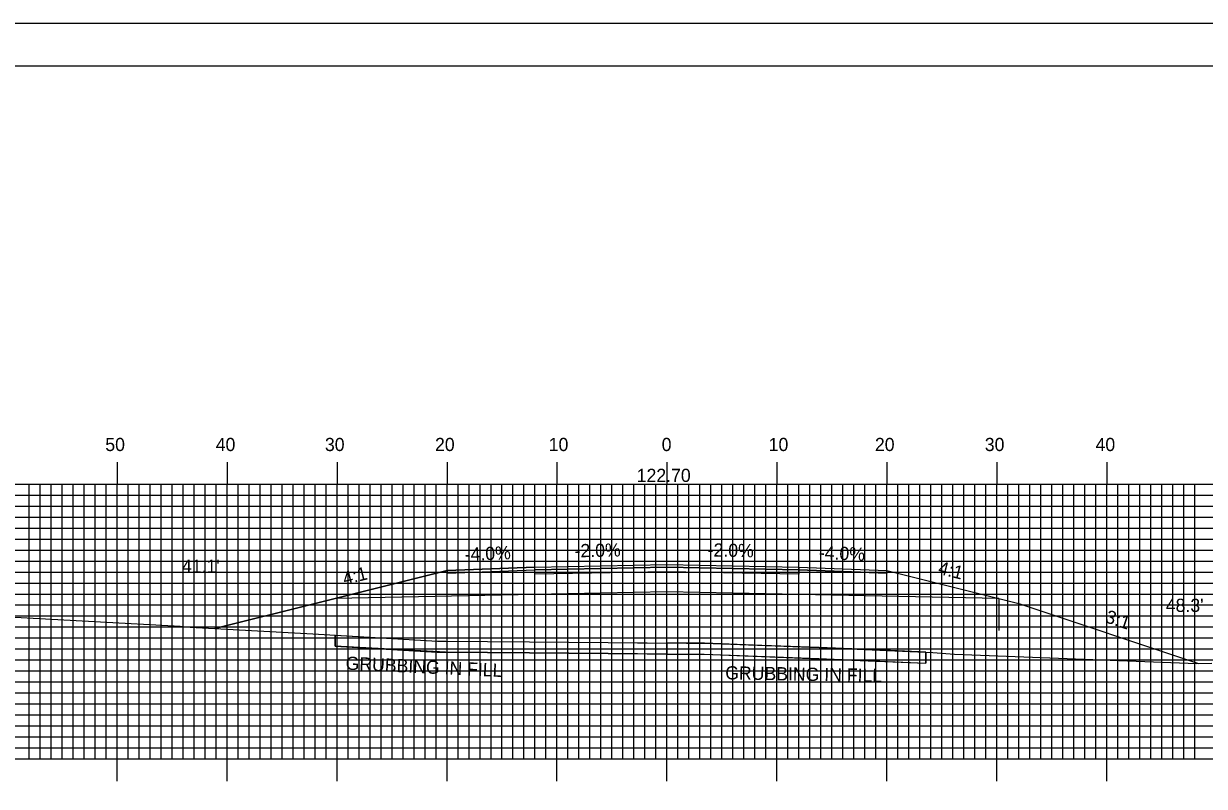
# Model space of a CAD drawing. Extents: x 1780680 to 1781023, y 442591 to 442811.
# Drawn here: x 1780786.9 to 1780894.2, y 442741.2 to 442810.5 of the extents above; entities that cross this region are included whole.
import ezdxf

# ---------------------------------------------------------------- set-up
doc = ezdxf.new("R2010")
doc.units = 0
for name, color, linetype in [('ANNOTATION', 7, 'Continuous'), ('BORDER', 7, 'Continuous'), ('D_Roadway_Centerline', 7, 'Continuous'), ('D_Roadway_Centerline_Text', 7, 'Continuous'), ('D_Roadway_Edge_Shoulder', 7, 'Continuous'), ('D_Roadway_Edge_TW', 7, 'Continuous'), ('D_Roadway_Pavement', 7, 'Continuous'), ('D_Roadway_SlopeLines', 7, 'Continuous'), ('D_Roadway_SubGrade', 7, 'Continuous'), ('D_Text_Standard', 7, 'Continuous'), ('GRUBBING IN FILL', 7, 'Continuous'), ('H_V ANNOTATION', 7, 'Continuous'), ('MAJOR', 7, 'Continuous'), ('MINOR', 7, 'Continuous'), ('PLOT BOUNDARY', 7, 'Continuous'), ('S_Roadway_Centerline', 7, 'Continuous')]:
    doc.layers.add(name, color=color, linetype=linetype)

msp = doc.modelspace()

# ---------------------------------------------------------------- linework, layer by layer
at = {"layer": 'BORDER'}
msp.add_lwpolyline([(1780695.78, 442596.67), (1781015.78, 442596.67), (1781015.78, 442806.67), (1780695.78, 442806.67)], close=True, dxfattribs=at)
at = {"layer": 'D_Roadway_Centerline'}
msp.add_lwpolyline([(1780804.27, 442755.53), (1780813.38, 442757.8), (1780815.21, 442758.26), (1780825.38, 442760.8), (1780833.38, 442761.12), (1780845.38, 442761.36), (1780857.38, 442761.12), (1780865.38, 442760.8), (1780875.56, 442758.26), (1780877.38, 442757.8), (1780893.72, 442752.36)], dxfattribs=at)
at = {"layer": 'D_Roadway_Edge_Shoulder'}
for points in [[(1780833.38, 442761.12), (1780825.38, 442760.8), (1780825.38, 442760.55), (1780833.38, 442760.87)], [(1780857.38, 442761.12), (1780865.38, 442760.8), (1780865.38, 442760.55), (1780857.38, 442760.87)]]:
    msp.add_lwpolyline(points, close=True, dxfattribs=at)
at = {"layer": 'D_Roadway_Edge_TW'}
msp.add_lwpolyline([(1780833.38, 442760.87), (1780833.38, 442761.12), (1780845.38, 442761.36), (1780857.38, 442761.12), (1780857.38, 442760.87), (1780845.38, 442761.11)], close=True, dxfattribs=at)
at = {"layer": 'D_Roadway_Pavement'}
msp.add_lwpolyline([(1780833.38, 442760.46), (1780833.38, 442760.87), (1780845.38, 442761.11), (1780857.38, 442760.87), (1780857.38, 442760.46), (1780845.38, 442760.7)], close=True, dxfattribs=at)
at = {"layer": 'D_Roadway_SlopeLines'}
for points in [[(1780825.38, 442760.8), (1780815.21, 442758.26), (1780813.38, 442757.8), (1780804.27, 442755.53)], [(1780865.38, 442760.8), (1780877.38, 442757.8), (1780893.72, 442752.36)]]:
    msp.add_lwpolyline(points, dxfattribs=at)
at = {"layer": 'D_Roadway_SubGrade'}
msp.add_lwpolyline([(1780833.38, 442758.62), (1780815.21, 442758.26), (1780825.38, 442760.8), (1780825.38, 442760.55), (1780833.38, 442760.87), (1780845.38, 442761.11), (1780857.38, 442760.87), (1780865.38, 442760.55), (1780865.38, 442760.8), (1780875.56, 442758.26), (1780857.38, 442758.62), (1780845.38, 442758.86)], close=True, dxfattribs=at)
at = {"layer": 'GRUBBING IN FILL'}
for p, q in [((1780875.56, 442758.26), (1780875.56, 442755.36)), ((1780875.56, 442758.26), (1780875.56, 442755.36)), ((1780815.21, 442754.92), (1780815.21, 442753.92)), ((1780815.21, 442754.92), (1780815.21, 442753.92)), ((1780868.91, 442753.39), (1780868.91, 442752.39)), ((1780868.91, 442753.39), (1780868.91, 442752.39))]:
    msp.add_line(p, q, dxfattribs=at)
for points in [[(1780815.21, 442753.92), (1780815.21, 442754.92), (1780818.85, 442754.71), (1780824.52, 442754.39), (1780829.07, 442754.35), (1780832.88, 442754.32), (1780840.02, 442754.25), (1780845.38, 442754.2), (1780845.38, 442753.2), (1780840.02, 442753.25), (1780832.87, 442753.32), (1780825.25, 442753.38)], [(1780815.21, 442753.92), (1780815.21, 442754.92), (1780818.85, 442754.71), (1780824.52, 442754.39), (1780829.07, 442754.35), (1780832.88, 442754.32), (1780840.02, 442754.25), (1780845.38, 442754.2), (1780845.38, 442753.2), (1780840.02, 442753.25), (1780832.87, 442753.32), (1780825.25, 442753.38)], [(1780845.38, 442753.2), (1780848.77, 442753.2), (1780853.98, 442753), (1780853.98, 442753), (1780868.91, 442752.39), (1780868.91, 442753.39), (1780864.39, 442753.59), (1780859.23, 442753.81), (1780854.01, 442754), (1780848.79, 442754.2), (1780845.38, 442754.2)], [(1780845.38, 442753.2), (1780848.77, 442753.2), (1780853.98, 442753), (1780853.98, 442753), (1780868.91, 442752.39), (1780868.91, 442753.39), (1780864.39, 442753.59), (1780859.23, 442753.81), (1780854.01, 442754), (1780848.79, 442754.2), (1780845.38, 442754.2)]]:
    msp.add_lwpolyline(points, close=True, dxfattribs=at)
msp.add_lwpolyline([(1780815.21, 442753.92), (1780824.49, 442753.39), (1780825.25, 442753.38), (1780832.87, 442753.32), (1780847.16, 442753.19), (1780847.98, 442753.2), (1780848.77, 442753.2), (1780859.19, 442752.81), (1780868.91, 442752.39)], dxfattribs=at)
msp.add_lwpolyline([(1780815.21, 442753.92), (1780824.49, 442753.39), (1780825.25, 442753.38), (1780832.87, 442753.32), (1780847.16, 442753.19), (1780847.98, 442753.2), (1780848.77, 442753.2), (1780859.19, 442752.81), (1780868.91, 442752.39)], dxfattribs=at)
at = {"layer": 'MAJOR'}
for p, q in [((1780795.38, 442770.67), (1780795.38, 442768.67)), ((1780805.38, 442770.67), (1780805.38, 442768.67)), ((1780815.38, 442770.67), (1780815.38, 442768.67)), ((1780825.38, 442770.67), (1780825.38, 442768.67)), ((1780835.38, 442770.67), (1780835.38, 442768.67)), ((1780845.38, 442770.67), (1780845.38, 442768.67)), ((1780855.38, 442770.67), (1780855.38, 442768.67)), ((1780865.38, 442770.67), (1780865.38, 442768.67)), ((1780875.38, 442770.67), (1780875.38, 442768.67)), ((1780885.38, 442770.67), (1780885.38, 442768.67)), ((1780705.38, 442768.67), (1780985.38, 442768.67)), ((1780705.38, 442768.67), (1780985.38, 442768.67)), ((1780795.38, 442743.67), (1780795.38, 442768.67)), ((1780805.38, 442743.67), (1780805.38, 442768.67)), ((1780815.38, 442743.67), (1780815.38, 442768.67)), ((1780825.38, 442743.67), (1780825.38, 442768.67)), ((1780835.38, 442743.67), (1780835.38, 442768.67)), ((1780845.38, 442743.67), (1780845.38, 442768.67)), ((1780855.38, 442743.67), (1780855.38, 442768.67)), ((1780865.38, 442743.67), (1780865.38, 442768.67)), ((1780875.38, 442743.67), (1780875.38, 442768.67)), ((1780885.38, 442743.67), (1780885.38, 442768.67)), ((1780705.38, 442763.67), (1780985.38, 442763.67)), ((1780705.38, 442758.67), (1780985.38, 442758.67)), ((1780705.38, 442753.67), (1780985.38, 442753.67)), ((1780705.38, 442748.67), (1780985.38, 442748.67)), ((1780705.38, 442743.67), (1780985.38, 442743.67)), ((1780705.38, 442743.67), (1780985.38, 442743.67)), ((1780795.38, 442741.66), (1780795.38, 442743.67)), ((1780805.38, 442741.66), (1780805.38, 442743.67)), ((1780815.38, 442741.66), (1780815.38, 442743.67)), ((1780825.38, 442741.66), (1780825.38, 442743.67)), ((1780835.38, 442741.66), (1780835.38, 442743.67)), ((1780845.38, 442741.66), (1780845.38, 442743.67)), ((1780855.38, 442741.66), (1780855.38, 442743.67)), ((1780865.38, 442741.66), (1780865.38, 442743.67)), ((1780875.38, 442741.66), (1780875.38, 442743.67)), ((1780885.38, 442741.66), (1780885.38, 442743.67))]:
    msp.add_line(p, q, dxfattribs=at)
at = {"layer": 'MINOR'}
for p, q in [((1780787.38, 442743.67), (1780787.38, 442768.67)), ((1780788.38, 442743.67), (1780788.38, 442768.67)), ((1780789.38, 442743.67), (1780789.38, 442768.67)), ((1780790.38, 442743.67), (1780790.38, 442768.67)), ((1780791.38, 442743.67), (1780791.38, 442768.67)), ((1780792.38, 442743.67), (1780792.38, 442768.67)), ((1780793.38, 442743.67), (1780793.38, 442768.67)), ((1780794.38, 442743.67), (1780794.38, 442768.67)), ((1780796.38, 442743.67), (1780796.38, 442768.67)), ((1780797.38, 442743.67), (1780797.38, 442768.67)), ((1780798.38, 442743.67), (1780798.38, 442768.67)), ((1780799.38, 442743.67), (1780799.38, 442768.67)), ((1780800.38, 442743.67), (1780800.38, 442768.67)), ((1780801.38, 442743.67), (1780801.38, 442768.67)), ((1780802.38, 442743.67), (1780802.38, 442768.67)), ((1780803.38, 442743.67), (1780803.38, 442768.67)), ((1780804.38, 442743.67), (1780804.38, 442768.67)), ((1780806.38, 442743.67), (1780806.38, 442768.67)), ((1780807.38, 442743.67), (1780807.38, 442768.67)), ((1780808.38, 442743.67), (1780808.38, 442768.67)), ((1780809.38, 442743.67), (1780809.38, 442768.67)), ((1780810.38, 442743.67), (1780810.38, 442768.67)), ((1780811.38, 442743.67), (1780811.38, 442768.67)), ((1780812.38, 442743.67), (1780812.38, 442768.67)), ((1780813.38, 442743.67), (1780813.38, 442768.67)), ((1780814.38, 442743.67), (1780814.38, 442768.67)), ((1780816.38, 442743.67), (1780816.38, 442768.67)), ((1780817.38, 442743.67), (1780817.38, 442768.67)), ((1780818.38, 442743.67), (1780818.38, 442768.67)), ((1780819.38, 442743.67), (1780819.38, 442768.67)), ((1780820.38, 442743.67), (1780820.38, 442768.67)), ((1780821.38, 442743.67), (1780821.38, 442768.67)), ((1780822.38, 442743.67), (1780822.38, 442768.67)), ((1780823.38, 442743.67), (1780823.38, 442768.67)), ((1780824.38, 442743.67), (1780824.38, 442768.67)), ((1780826.38, 442743.67), (1780826.38, 442768.67)), ((1780827.38, 442743.67), (1780827.38, 442768.67)), ((1780828.38, 442743.67), (1780828.38, 442768.67)), ((1780829.38, 442743.67), (1780829.38, 442768.67)), ((1780830.38, 442743.67), (1780830.38, 442768.67)), ((1780831.38, 442743.67), (1780831.38, 442768.67)), ((1780832.38, 442743.67), (1780832.38, 442768.67)), ((1780833.38, 442743.67), (1780833.38, 442768.67)), ((1780834.38, 442743.67), (1780834.38, 442768.67)), ((1780836.38, 442743.67), (1780836.38, 442768.67)), ((1780837.38, 442743.67), (1780837.38, 442768.67)), ((1780838.38, 442743.67), (1780838.38, 442768.67)), ((1780839.38, 442743.67), (1780839.38, 442768.67)), ((1780840.38, 442743.67), (1780840.38, 442768.67)), ((1780841.38, 442743.67), (1780841.38, 442768.67)), ((1780842.38, 442743.67), (1780842.38, 442768.67)), ((1780843.38, 442743.67), (1780843.38, 442768.67)), ((1780844.38, 442743.67), (1780844.38, 442768.67)), ((1780846.38, 442743.67), (1780846.38, 442768.67)), ((1780847.38, 442743.67), (1780847.38, 442768.67)), ((1780848.38, 442743.67), (1780848.38, 442768.67)), ((1780849.38, 442743.67), (1780849.38, 442768.67)), ((1780850.38, 442743.67), (1780850.38, 442768.67)), ((1780851.38, 442743.67), (1780851.38, 442768.67)), ((1780852.38, 442743.67), (1780852.38, 442768.67)), ((1780853.38, 442743.67), (1780853.38, 442768.67)), ((1780854.38, 442743.67), (1780854.38, 442768.67)), ((1780856.38, 442743.67), (1780856.38, 442768.67)), ((1780857.38, 442743.67), (1780857.38, 442768.67)), ((1780858.38, 442743.67), (1780858.38, 442768.67)), ((1780859.38, 442743.67), (1780859.38, 442768.67)), ((1780860.38, 442743.67), (1780860.38, 442768.67)), ((1780861.38, 442743.67), (1780861.38, 442768.67)), ((1780862.38, 442743.67), (1780862.38, 442768.67)), ((1780863.38, 442743.67), (1780863.38, 442768.67)), ((1780864.38, 442743.67), (1780864.38, 442768.67)), ((1780866.38, 442743.67), (1780866.38, 442768.67)), ((1780867.38, 442743.67), (1780867.38, 442768.67)), ((1780868.38, 442743.67), (1780868.38, 442768.67)), ((1780869.38, 442743.67), (1780869.38, 442768.67)), ((1780870.38, 442743.67), (1780870.38, 442768.67)), ((1780871.38, 442743.67), (1780871.38, 442768.67)), ((1780872.38, 442743.67), (1780872.38, 442768.67)), ((1780873.38, 442743.67), (1780873.38, 442768.67)), ((1780874.38, 442743.67), (1780874.38, 442768.67)), ((1780876.38, 442743.67), (1780876.38, 442768.67)), ((1780877.38, 442743.67), (1780877.38, 442768.67)), ((1780878.38, 442743.67), (1780878.38, 442768.67)), ((1780879.38, 442743.67), (1780879.38, 442768.67)), ((1780880.38, 442743.67), (1780880.38, 442768.67)), ((1780881.38, 442743.67), (1780881.38, 442768.67)), ((1780882.38, 442743.67), (1780882.38, 442768.67)), ((1780883.38, 442743.67), (1780883.38, 442768.67)), ((1780884.38, 442743.67), (1780884.38, 442768.67)), ((1780886.38, 442743.67), (1780886.38, 442768.67)), ((1780887.38, 442743.67), (1780887.38, 442768.67)), ((1780888.38, 442743.67), (1780888.38, 442768.67)), ((1780889.38, 442743.67), (1780889.38, 442768.67)), ((1780890.38, 442743.67), (1780890.38, 442768.67)), ((1780891.38, 442743.67), (1780891.38, 442768.67)), ((1780892.38, 442743.67), (1780892.38, 442768.67)), ((1780893.38, 442743.67), (1780893.38, 442768.67)), ((1780705.38, 442767.67), (1780985.38, 442767.67)), ((1780705.38, 442766.67), (1780985.38, 442766.67)), ((1780705.38, 442765.67), (1780985.38, 442765.67)), ((1780705.38, 442764.67), (1780985.38, 442764.67)), ((1780705.38, 442762.67), (1780985.38, 442762.67)), ((1780705.38, 442761.67), (1780985.38, 442761.67)), ((1780705.38, 442760.67), (1780985.38, 442760.67)), ((1780705.38, 442759.67), (1780985.38, 442759.67)), ((1780705.38, 442757.67), (1780985.38, 442757.67)), ((1780705.38, 442756.67), (1780985.38, 442756.67)), ((1780705.38, 442755.67), (1780985.38, 442755.67)), ((1780705.38, 442754.67), (1780985.38, 442754.67)), ((1780705.38, 442752.67), (1780985.38, 442752.67)), ((1780705.38, 442751.67), (1780985.38, 442751.67)), ((1780705.38, 442750.67), (1780985.38, 442750.67)), ((1780705.38, 442749.67), (1780985.38, 442749.67)), ((1780705.38, 442747.67), (1780985.38, 442747.67)), ((1780705.38, 442746.67), (1780985.38, 442746.67)), ((1780705.38, 442745.67), (1780985.38, 442745.67)), ((1780705.38, 442744.67), (1780985.38, 442744.67))]:
    msp.add_line(p, q, dxfattribs=at)
at = {"layer": 'PLOT BOUNDARY'}
msp.add_lwpolyline([(1780679.59, 442590.55), (1781019.59, 442590.55), (1781019.59, 442810.55), (1780679.59, 442810.55)], close=True, dxfattribs=at)
at = {"layer": 'S_Roadway_Centerline'}
msp.add_lwpolyline([(1780777.71, 442757.02), (1780801.11, 442755.74), (1780802.04, 442755.65), (1780813.18, 442755.04), (1780824.52, 442754.39), (1780825.26, 442754.38), (1780832.88, 442754.32), (1780847.16, 442754.19), (1780847.97, 442754.2), (1780848.79, 442754.2), (1780859.23, 442753.81), (1780869.55, 442753.36), (1780871.54, 442753.21), (1780893.56, 442752.35), (1780894.93, 442752.37)], dxfattribs=at)

# ---------------------------------------------------------------- texts
at = {"layer": 'ANNOTATION'}
for s, rotation, p in [('-4.0%', 2.2906, (1780827.01, 442761.67)), ('-2.0%', 1.1458, (1780836.99, 442762)), ('-2.0%', 358.8542, (1780849.07, 442762.09)), ('-4.0%', 357.7094, (1780859.17, 442761.85)), ('4:1', 14.0362, (1780816.07, 442759.48)), ('4:1', 345.9638, (1780869.97, 442760.52)), ('3:1', 341.5652, (1780885.15, 442756.12))]:
    msp.add_text(s, height=1.2, rotation=rotation, dxfattribs=at).set_placement(p)
at = {"layer": 'D_Roadway_Centerline'}
for s in ['C', 'L']:
    msp.add_text(s, height=0.0146, dxfattribs=at).set_placement((1780845.38, 442761.36))
at = {"layer": 'D_Roadway_Centerline_Text'}
msp.add_text('122.70', height=1.2, dxfattribs=at).set_placement((1780842.63, 442768.86))
at = {"layer": 'D_Text_Standard'}
for s, p in [("41.1'", (1780801.28, 442760.6)), ("48.3'", (1780890.74, 442757.04))]:
    msp.add_text(s, height=1.2, dxfattribs=at).set_placement(p)
at = {"layer": 'GRUBBING IN FILL'}
for rotation, p in [(357.2948, (1780816.14, 442751.79)), (358.9728, (1780850.67, 442750.91))]:
    msp.add_text('GRUBBING IN FILL', height=1.2, rotation=rotation, dxfattribs=at).set_placement(p)
at = {"layer": 'H_V ANNOTATION'}
for s, p in [('50', (1780794.31, 442771.67)), ('40', (1780804.35, 442771.67)), ('30', (1780814.28, 442771.67)), ('20', (1780824.29, 442771.67)), ('10', (1780834.63, 442771.67)), ('0', (1780844.9, 442771.67)), ('10', (1780854.63, 442771.67)), ('20', (1780864.29, 442771.67)), ('30', (1780874.28, 442771.67)), ('40', (1780884.35, 442771.67))]:
    msp.add_text(s, height=1.2, dxfattribs=at).set_placement(p)

doc.saveas('drawing.dxf')
